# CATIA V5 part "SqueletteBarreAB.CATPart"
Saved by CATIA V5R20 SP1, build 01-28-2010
Part number: SqueletteBarreAB
Publications: "EpaisseurABetDC", "DiametrePivotABetDC", "DiametreTrousABetDC", "LongueurAB", "LargeurABetDC", "Point.1", "Point.2", "Droite.1", "Droite.2", "Droite.3"
Bounding box of the stored display mesh (mm): x -20 to 20, y -50 to 50, z 0 to 0
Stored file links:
  C:\Documents and Settings\ndumont\Bureau\ndumont_CAO\SqueletteBarreAB.CATPart
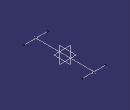
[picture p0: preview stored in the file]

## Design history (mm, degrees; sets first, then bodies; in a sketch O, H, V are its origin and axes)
Parameters
  EpaisseurABetDC = 20 mm
  DiametrePivotABetDC = 40 mm
  DiametreTrousABetDC = 18 mm
  LongueurAB = 100 mm
  LargeurABetDC = 30 mm
Set1
  Point1: (0, 50 {= LongueurAB /2}, 0)
  Point2: (0, -50 {= -LongueurAB /2}, 0)
  Line1: type PtPt, FirstPoint Point2, SecondPoint Point1
  Line2: type PtDir, RefPoint Point2, Direction yz-plane, Start -20, End 20
  Line3: type PtDir, RefPoint Point1, Direction yz-plane, Start -20, End 20
Body1 (main body)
